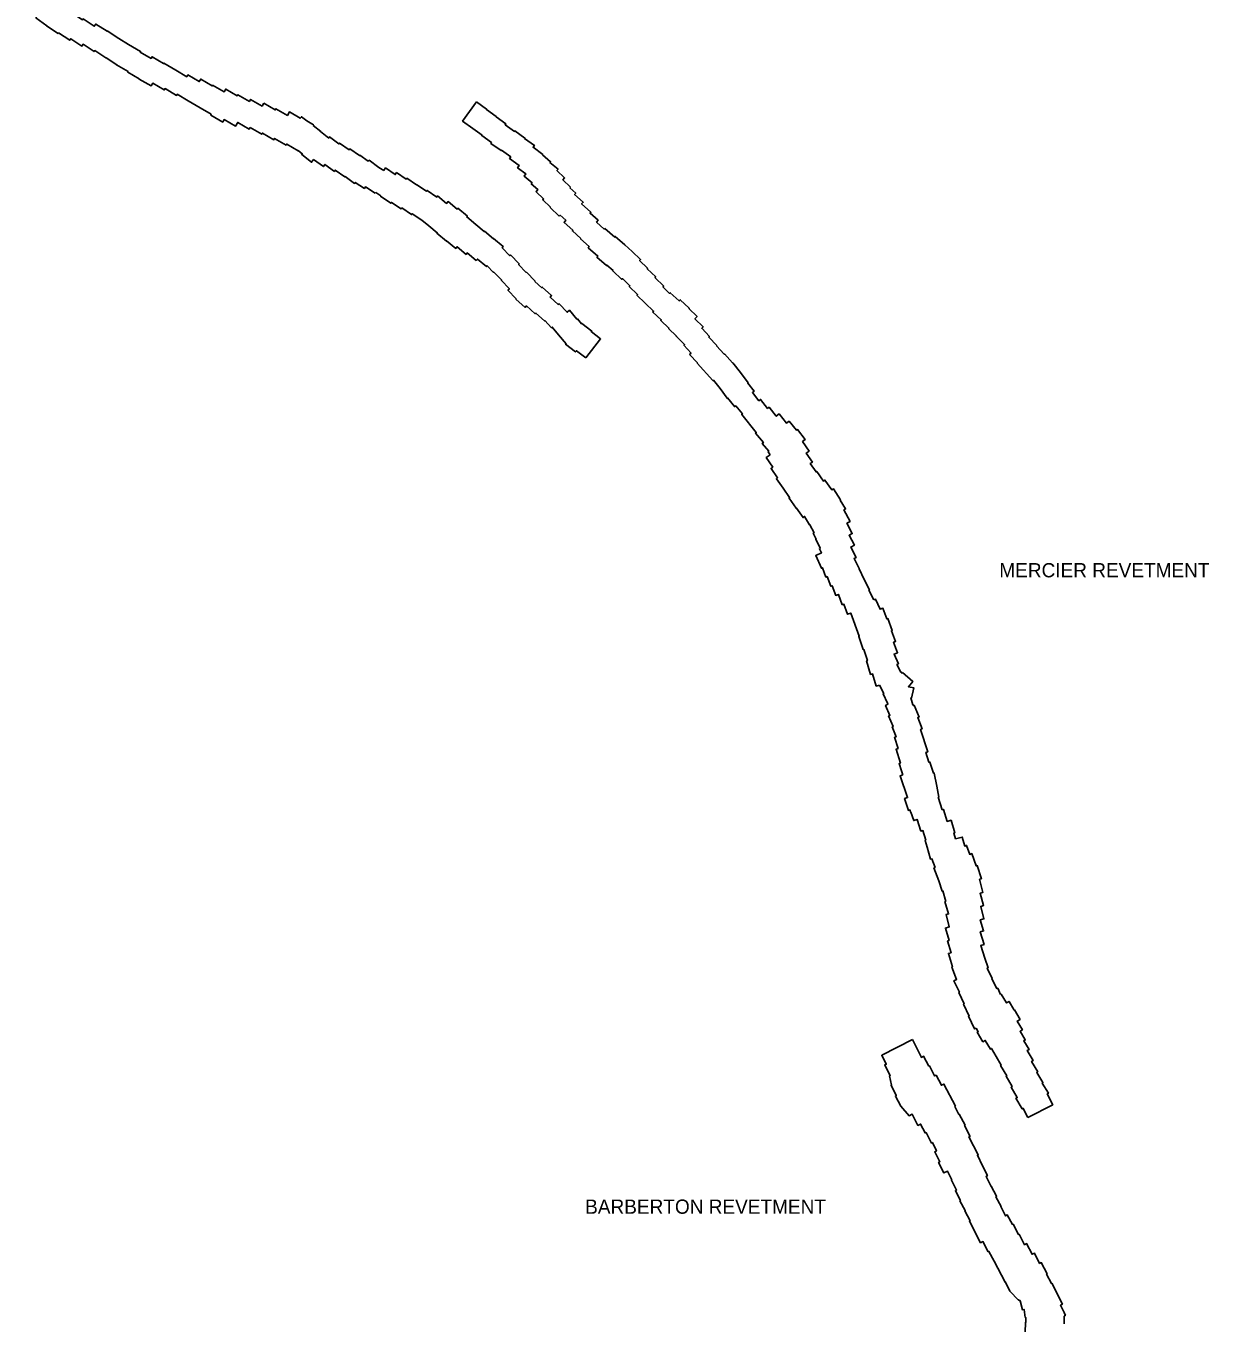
# Model space of a CAD drawing. Extents: x 2650582 to 3923188, y 277893 to 989177.
# Drawn here: x 3136380 to 3149698, y 821343 to 835938 of the extents above; entities that cross this region are included whole.
import ezdxf

# ---------------------------------------------------------------- set-up
doc = ezdxf.new("R2010")
doc.units = 0
doc.layers.add('Level 3', color=7, linetype='Continuous')

msp = doc.modelspace()

# ---------------------------------------------------------------- linework, layer by layer
at = {"layer": 'Level 3'}
for points in [[(3136545, 836334), (3136549, 836338), (3136669, 836240), (3136666, 836236), (3136763, 836165), (3136773, 836182), (3136904, 836097), (3136897, 836085), (3137017, 836006), (3137024, 836017), (3137150, 835935), (3137166, 835960), (3137293, 835878), (3137296, 835883), (3137427, 835798), (3137534, 835728)], [(3137402, 835501), (3137282, 835579), (3137281, 835578), (3137155, 835660), (3137148, 835650), (3137023, 835732), (3137010, 835712), (3136884, 835794), (3136873, 835778), (3136748, 835860), (3136743, 835853), (3136613, 835939), (3136615, 835941), (3136493, 836031), (3136498, 836038), (3136380, 836134), (3136390, 836146)], [(3137534, 835728), (3137535, 835730), (3137670, 835652), (3137666, 835644), (3137789, 835572), (3137800, 835591), (3137930, 835515), (3137933, 835520), (3138067, 835440), (3138066, 835439), (3138191, 835366), (3138203, 835388), (3138332, 835312), (3138349, 835340), (3138478, 835264), (3138482, 835271), (3138611, 835195), (3138630, 835228), (3138759, 835152), (3138767, 835164), (3138896, 835089), (3138909, 835112), (3139039, 835036), (3139058, 835070)], [(3138905, 834796), (3138894, 834778), (3138765, 834853), (3138739, 834809), (3138610, 834884), (3138595, 834857), (3138460, 834936), (3138464, 834944), (3138340, 835016), (3138340, 835015), (3138205, 835094), (3138207, 835097), (3138083, 835169), (3138076, 835157), (3137946, 835233), (3137937, 835218), (3137808, 835293), (3137790, 835263), (3137655, 835341), (3137655, 835342), (3137526, 835418), (3137530, 835424), (3137401, 835499), (3137402, 835501)], [(3139058, 835070), (3139187, 834994), (3139194, 835007), (3139324, 834932), (3139347, 834970), (3139468, 834899), (3139482, 834917), (3139543, 834869), (3139617, 834826), (3139612, 834818)], [(3141453, 835084), (3141296, 834867), (3141409, 834785), (3141409, 834786), (3141515, 834709), (3141511, 834704), (3141620, 834625), (3141615, 834617), (3141728, 834535), (3141732, 834540), (3141837, 834464), (3141824, 834447), (3141934, 834367), (3141915, 834342), (3142009, 834274), (3141987, 834248), (3142079, 834172), (3142068, 834160), (3142144, 834096), (3142122, 834073), (3142208, 833991), (3142198, 833981), (3142284, 833898), (3142282, 833896), (3142383, 833799)], [(3142502, 834117), (3142509, 834124), (3142424, 834207), (3142444, 834228), (3142358, 834311), (3142370, 834326), (3142279, 834402), (3142286, 834411), (3142195, 834488), (3142198, 834493), (3142089, 834573), (3142104, 834593), (3141994, 834672), (3141997, 834676), (3141884, 834758), (3141878, 834751), (3141773, 834827), (3141781, 834838), (3141672, 834917), (3141673, 834918), (3141563, 834998), (3141566, 835002), (3141453, 835084)], [(3139446, 834535), (3139445, 834533), (3139316, 834609), (3139309, 834597), (3139180, 834673), (3139171, 834658), (3139042, 834733), (3139034, 834720), (3138905, 834796)], [(3139612, 834818), (3139698, 834751), (3139696, 834749), (3139788, 834677), (3139797, 834689), (3139904, 834611), (3139910, 834620), (3140017, 834543), (3140027, 834556), (3140134, 834479), (3140138, 834484), (3140232, 834416), (3140242, 834427), (3140354, 834345), (3140408, 834310)], [(3140313, 834055), (3140202, 834127), (3140191, 834110), (3140088, 834177), (3140080, 834166), (3139973, 834244), (3139970, 834240), (3139863, 834317), (3139853, 834302), (3139746, 834380), (3139728, 834355), (3139618, 834435), (3139595, 834405), (3139485, 834491), (3139491, 834500), (3139446, 834535)], [(3140408, 834310), (3140428, 834340), (3140537, 834266), (3140553, 834289), (3140662, 834215), (3140668, 834224), (3140778, 834150), (3140779, 834152), (3140888, 834079), (3140895, 834087), (3141004, 834013), (3141014, 834025), (3141115, 833941), (3141133, 833961), (3141234, 833876), (3141242, 833886), (3141349, 833796), (3141343, 833789), (3141445, 833705), (3141444, 833704), (3141539, 833624), (3141542, 833628), (3141643, 833543), (3141645, 833546), (3141753, 833456), (3141741, 833442), (3141826, 833353), (3141836, 833362), (3141933, 833261), (3141925, 833254), (3142011, 833164), (3142014, 833167), (3142111, 833066), (3142109, 833064), (3142187, 832993), (3142192, 832999), (3142297, 832905), (3142280, 832887), (3142372, 832804), (3142382, 832813), (3142471, 832717), (3142498, 832739), (3142582, 832638), (3142587, 832642), (3142635, 832586), (3142639, 832591), (3142749, 832505), (3142744, 832499), (3142848, 832417), (3142681, 832203)], [(3144424, 832038), (3144336, 832148), (3144334, 832146), (3144244, 832247), (3144240, 832244), (3144155, 832339), (3144157, 832341), (3144066, 832437), (3144074, 832444), (3143988, 832536), (3144004, 832552), (3143911, 832643), (3143935, 832668), (3143843, 832757), (3143846, 832762), (3143746, 832857), (3143735, 832845), (3143632, 832937), (3143625, 832928), (3143550, 833001), (3143560, 833012), (3143461, 833107), (3143469, 833116), (3143374, 833207), (3143378, 833212), (3143287, 833298), (3143299, 833311), (3143205, 833400), (3143121, 833476), (3143014, 833569), (3143008, 833563), (3142896, 833659), (3142890, 833653), (3142803, 833732), (3142820, 833751), (3142731, 833831), (3142740, 833841), (3142635, 833935), (3142653, 833955), (3142556, 834042), (3142570, 834058), (3142502, 834117)], [(3142681, 832203), (3142577, 832284), (3142566, 832270), (3142455, 832356), (3142460, 832363), (3142375, 832464), (3142376, 832464), (3142304, 832549), (3142296, 832542), (3142220, 832623), (3142218, 832620), (3142120, 832708), (3142111, 832699), (3142013, 832787), (3141999, 832771), (3141895, 832865), (3141898, 832869), (3141805, 832965), (3141823, 832982), (3141731, 833077), (3141734, 833080), (3141647, 833169), (3141643, 833164), (3141571, 833239), (3141564, 833230), (3141462, 833315), (3141449, 833299), (3141348, 833384), (3141334, 833368), (3141233, 833453), (3141218, 833434), (3141116, 833519), (3141114, 833516), (3141007, 833606), (3141011, 833611), (3140916, 833690), (3140914, 833689), (3140838, 833753), (3140837, 833751), (3140727, 833825), (3140721, 833816), (3140612, 833890), (3140604, 833879), (3140495, 833953), (3140489, 833944), (3140373, 834022), (3140375, 834025), (3140318, 834063), (3140313, 834055)], [(3142383, 833799), (3142392, 833809), (3142457, 833751), (3142437, 833728), (3142537, 833639), (3142531, 833632), (3142626, 833547), (3142623, 833544), (3142720, 833455), (3142710, 833443), (3142819, 833349), (3142808, 833335), (3142915, 833242), (3142920, 833248), (3142989, 833186), (3142986, 833182), (3143087, 833087), (3143094, 833095), (3143179, 833014), (3143172, 833007), (3143265, 832917), (3143258, 832910), (3143445, 832729), (3143436, 832718), (3143532, 832632), (3143525, 832625), (3143617, 832538), (3143614, 832535), (3143705, 832446), (3143702, 832442), (3143794, 832353), (3143786, 832345), (3143868, 832258), (3143851, 832241), (3143939, 832147), (3143936, 832144), (3144113, 831947), (3144118, 831951), (3144193, 831858)], [(3145925, 829482), (3145869, 829589), (3145875, 829592), (3145815, 829710), (3145817, 829711), (3145758, 829831), (3145760, 829832), (3145702, 829946), (3145724, 829956), (3145665, 830074), (3145706, 830096), (3145646, 830207), (3145682, 830226), (3145622, 830343), (3145657, 830363), (3145588, 830492), (3145606, 830504), (3145547, 830604), (3145549, 830605), (3145470, 830730), (3145452, 830718), (3145373, 830829), (3145356, 830817), (3145282, 830926), (3145274, 830921), (3145208, 831013), (3145234, 831031), (3145164, 831132), (3145196, 831154), (3145122, 831262), (3145152, 831285), (3145067, 831397), (3145055, 831388), (3144971, 831490), (3144943, 831467), (3144858, 831572), (3144826, 831546), (3144745, 831648), (3144729, 831635), (3144649, 831735), (3144631, 831721), (3144557, 831812), (3144577, 831828), (3144505, 831919), (3144509, 831921), (3144424, 832038)], [(3144193, 831858), (3144273, 831749), (3144277, 831753), (3144358, 831653), (3144371, 831664), (3144445, 831573), (3144438, 831567), (3144601, 831362), (3144594, 831357), (3144681, 831251), (3144669, 831241), (3144742, 831152), (3144734, 831145), (3144758, 831113)], [(3144758, 831113), (3144713, 831081), (3144787, 830975), (3144767, 830960), (3144841, 830854), (3144828, 830844), (3144902, 830738), (3144902, 830737), (3144976, 830631), (3144970, 830626), (3145050, 830511), (3145053, 830514), (3145128, 830407), (3145145, 830419), (3145202, 830324), (3145205, 830326), (3145252, 830235), (3145243, 830230), (3145276, 830165)], [(3145276, 830165), (3145270, 830162), (3145321, 830061), (3145312, 830056), (3145337, 830010), (3145270, 829980), (3145335, 829836), (3145345, 829841), (3145385, 829737), (3145399, 829742), (3145441, 829634), (3145455, 829639), (3145496, 829531), (3145525, 829542), (3145569, 829424)], [(3146246, 828665), (3146238, 828656), (3146231, 828670), (3146227, 828668), (3146184, 828752), (3146202, 828761), (3146153, 828871), (3146191, 828886), (3146146, 829003), (3146169, 829012), (3146123, 829132), (3146131, 829135), (3146083, 829269), (3146072, 829266), (3146026, 829387), (3145994, 829375), (3145943, 829490), (3145925, 829482)], [(3145569, 829424), (3145588, 829431), (3145629, 829319), (3145664, 829332), (3145761, 829072), (3145755, 829070), (3145805, 828921), (3145811, 828922), (3145853, 828797), (3145843, 828794), (3145887, 828641), (3145910, 828648), (3145951, 828510), (3145989, 828521)], [(3146364, 828301), (3146340, 828377), (3146350, 828375), (3146373, 828491), (3146313, 828502), (3146364, 828560), (3146246, 828665)], [(3145989, 828521), (3146037, 828428), (3146029, 828424), (3146079, 828318), (3146083, 828305), (3146057, 828293), (3146106, 828180), (3146091, 828174), (3146141, 828054), (3146132, 828051), (3146175, 827939), (3146158, 827934), (3146198, 827808), (3146174, 827799), (3146224, 827644), (3146209, 827639), (3146237, 827558), (3146234, 827557), (3146249, 827510)], [(3146647, 827259), (3146655, 827260), (3146634, 827386), (3146604, 827532), (3146596, 827530), (3146555, 827656), (3146545, 827653), (3146510, 827763), (3146532, 827771), (3146450, 828023), (3146467, 828030), (3146419, 828155), (3146433, 828161), (3146378, 828294), (3146369, 828290), (3146364, 828301)], [(3146249, 827510), (3146219, 827500), (3146304, 827255), (3146271, 827244), (3146314, 827111), (3146333, 827117), (3146335, 827110), (3146338, 827090), (3146342, 827090), (3146373, 826996), (3146412, 827010), (3146454, 826878), (3146477, 826885), (3146508, 826776), (3146501, 826774), (3146525, 826697)], [(3146845, 826790), (3146825, 826857), (3146835, 826860), (3146794, 827000), (3146751, 826987), (3146708, 827122), (3146695, 827118), (3146647, 827259)], [(3146525, 826697), (3146523, 826696), (3146562, 826563), (3146579, 826568), (3146614, 826469), (3146601, 826464), (3146655, 826320), (3146657, 826320), (3146694, 826202), (3146702, 826205), (3146733, 826088), (3146725, 826086), (3146765, 825947), (3146737, 825939), (3146774, 825800), (3146730, 825787), (3146772, 825649), (3146755, 825643), (3146794, 825510), (3146764, 825502), (3146809, 825352), (3146803, 825349), (3146856, 825209), (3146826, 825195), (3146888, 825065), (3146883, 825063), (3146941, 824935), (3146935, 824932), (3146997, 824798), (3146991, 824795), (3147057, 824653), (3147075, 824661)], [(3147351, 825039), (3147319, 825110), (3147310, 825106), (3147289, 825140), (3147254, 825219), (3147256, 825220), (3147201, 825338), (3147211, 825341), (3147172, 825448), (3147128, 825593), (3147165, 825604), (3147123, 825745), (3147159, 825756), (3147122, 825879), (3147164, 825891), (3147127, 826032), (3147159, 826042), (3147120, 826179), (3147153, 826188), (3147115, 826336), (3147136, 826343), (3147089, 826491), (3147078, 826487), (3147026, 826625), (3147004, 826616), (3146968, 826717), (3146948, 826710), (3146919, 826811), (3146845, 826790)], [(3147658, 823656), (3147938, 823799), (3147877, 823921), (3147889, 823928), (3147820, 824044), (3147827, 824048), (3147758, 824164), (3147769, 824171), (3147700, 824287), (3147717, 824297), (3147650, 824409), (3147671, 824421), (3147612, 824519), (3147628, 824529), (3147570, 824626), (3147597, 824643), (3147539, 824741), (3147571, 824760), (3147507, 824866), (3147504, 824865), (3147446, 824962), (3147418, 824946), (3147359, 825043), (3147351, 825039)], [(3147075, 824661), (3147099, 824621), (3147088, 824615), (3147152, 824508), (3147178, 824524), (3147236, 824426), (3147248, 824433), (3147302, 824344), (3147301, 824343), (3147359, 824246), (3147352, 824241), (3147421, 824125), (3147413, 824120), (3147482, 824005), (3147469, 823997), (3147538, 823881), (3147523, 823872), (3147595, 823752), (3147606, 823758), (3147658, 823656)], [(3146360, 824532), (3146013, 824356), (3146064, 824255), (3146047, 824247), (3146107, 824126), (3146099, 824124), (3146125, 824021), (3146119, 824018), (3146177, 823902), (3146168, 823897), (3146227, 823782), (3146229, 823783), (3146321, 823675), (3146356, 823692), (3146420, 823566), (3146451, 823582), (3146502, 823482), (3146512, 823487), (3146575, 823369), (3146583, 823373), (3146629, 823280), (3146610, 823270), (3146668, 823158), (3146653, 823150), (3146714, 823033), (3146753, 823053), (3146802, 822954), (3146797, 822951), (3146855, 822839), (3146842, 822832), (3146899, 822721), (3146894, 822718), (3146953, 822608), (3146949, 822606), (3147007, 822493), (3147000, 822489), (3147126, 822247), (3147153, 822260), (3147213, 822146), (3147220, 822150), (3147277, 822038), (3147280, 822040), (3147401, 821804), (3147404, 821806), (3147456, 821704), (3147454, 821701), (3147553, 821601), (3147556, 821605), (3147561, 821596), (3147567, 821599), (3147573, 821594)], [(3148067, 821422), (3148081, 821430), (3148066, 821459), (3148066, 821468), (3148062, 821468), (3148024, 821543), (3148048, 821556), (3147927, 821792), (3147923, 821790), (3147868, 821895), (3147874, 821898), (3147809, 822024), (3147791, 822015), (3147731, 822131), (3147705, 822117), (3147644, 822237), (3147621, 822225), (3147560, 822343), (3147553, 822339), (3147491, 822456), (3147485, 822453), (3147427, 822560), (3147407, 822549), (3147353, 822653), (3147356, 822655), (3147299, 822765), (3147307, 822769), (3147246, 822882), (3147244, 822881), (3147187, 822993), (3147203, 823002), (3147146, 823113), (3147149, 823114), (3147091, 823231), (3147099, 823235), (3146993, 823437), (3147007, 823444), (3146946, 823566), (3146952, 823568), (3146886, 823692), (3146883, 823690), (3146837, 823781), (3146842, 823784), (3146714, 824032), (3146686, 824018), (3146626, 824132), (3146609, 824123), (3146551, 824237), (3146545, 824234), (3146485, 824345), (3146460, 824332), (3146360, 824532)], [(3147573, 821594), (3147596, 821493), (3147616, 821497), (3147628, 821406), (3147634, 821407), (3147635, 821351), (3147633, 821352), (3147629, 821238)], [(3148068, 821336), (3148067, 821422)]]:
    msp.add_lwpolyline(points, dxfattribs=at)

# ---------------------------------------------------------------- texts
for s, p in [('MERCIER REVETMENT', (3147337, 829734)), ('BARBERTON REVETMENT', (3142675, 822573))]:
    msp.add_text(s, height=160, dxfattribs=at).set_placement(p)

doc.saveas('drawing.dxf')
